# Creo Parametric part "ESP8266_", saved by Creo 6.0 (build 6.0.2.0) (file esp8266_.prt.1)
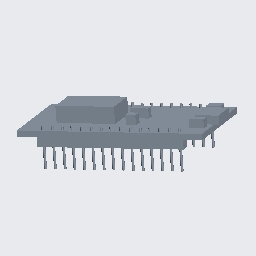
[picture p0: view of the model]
Units: Inch lbm Second (Pro/E Default); INCH, POUND, SECS

Created from: INLBS_PART_SOLID.PRT

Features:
  1. datum plane "RIGHT"
  2. datum plane "TOP"
  3. datum plane "FRONT"
  4. coordinate system
  5. sketch "Sketch 1"
  6. extrusion "Extrude 1"
  7. sketch "Sketch 2"
  8. extrusion "Extrude 2"
  9. sketch "Sketch 3"
  10. pattern "Pattern 1"
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
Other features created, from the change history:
  extrusion "Extrude 3"
  extrusion "Extrude 3 [3]"
  extrusion "Extrude 3 [4]"
  extrusion "Extrude 3 [5]"
  extrusion "Extrude 3 [6]"
  extrusion "Extrude 3 [7]"
  extrusion "Extrude 3 [8]"
  extrusion "Extrude 3 [9]"
  extrusion "Extrude 3 [10]"
  extrusion "Extrude 3 [11]"
  extrusion "Extrude 3 [12]"
  extrusion "Extrude 3 [13]"
  extrusion "Extrude 3 [14]"
  extrusion "Extrude 3 [15]"
  sketch "Sketch 4"
  extrusion "Extrude 4"
  sketch "Sketch 5"
  extrusion "Extrude 5"
  sketch "Sketch 6"
  extrusion "Extrude 6"
  sketch "Sketch 7"
  extrusion "Extrude 7"
  sketch "Sketch 8"
  extrusion "Extrude 8"

Surfaces: 72 plane, 30 cylinder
